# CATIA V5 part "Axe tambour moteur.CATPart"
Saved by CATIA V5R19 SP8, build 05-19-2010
Part number: Axe tambour moteur
Nomenclature: 39a
Material "Acier": density 7860 kg/m3, Young's modulus 2e+11 Pa, Poisson ratio 0.266, thermal expansion 1.17e-05 1/K
Bounding box of the stored display mesh (mm): x -270 to 270, y -7.5 to 7.5, z -7.474 to 7.474
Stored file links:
  C:\Users\rphgr\Desktop\0_Tapis_TC520B_vitesse\Axe tambour moteur.CATPart
  D:\Programmes\DassaultSysteme\win_b64\reffiles\standard\MetricThickPitch.txt
  D:\Programmes\DassaultSysteme\win_b64\startup\materials\French\Catalog.CATMaterial
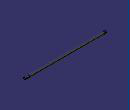
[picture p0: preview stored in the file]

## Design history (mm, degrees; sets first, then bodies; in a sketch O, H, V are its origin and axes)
AxisSystem1: origin (0, 0, 0), X (1, 0, 0), Y (0, 1, 0), Z (0, 0, 1)
Body1 (main body), material "Acier"
  Sketch1 on YZ plane of AxisSystem1, origin (0, 0, 0), H (0, 1, 0), V (0, 0, 1)
    circle A1 centre (0, 0) radius 7.5
    radius A1 = 7.5
  Pad1: profile Sketch1, direction (1, 0, 0), length 270, mirrored extent
  Chamfer1: length 0.5, angle 45, on start face of Pad1; end face of Pad1
  Sketch2 on ZX plane of AxisSystem1, origin (0, 0, 0), H (0, 0, 1), V (1, 0, 0)
    line L1 (6.75, 243) -> (11.7, 243)
    line L2 (11.7, 243) -> (11.7, 241.9)
    line L3 (11.7, 241.9) -> (6.75, 241.9)
    line L4 (6.75, 241.9) -> (6.75, 243)
    line L5 (6.7, -258.9) -> (11.7, -258.9)
    line L6 (11.7, -258.9) -> (11.7, -260)
    line L7 (11.7, -260) -> (6.7, -260)
    line L8 (6.7, -260) -> (6.7, -258.9)
    reference projected line E1 through (0, 0) direction (0, 1) from axis of face of Pad1 from Sketch1.A1
    reference intersected line E2 (7.5, -270) -> (-7.5, -270) from start face of Pad1
    reference projected line E3 through (0, 0) direction (0, 1) from axis of face of Pad1 from Sketch1.A1
    reference intersected line E4 (-7.5, 270) -> (7.5, 270) from end face of Pad1
    distance L5 L7 = 1.1
    distance L8 E1 = 6.7
    distance L6 L8 = 5
    distance L7 E2 = 10
    distance L4 E3 = 6.75
    distance L1 L3 = 1.1
    distance L1 E4 = 27
    horizontal: L1 H, L3 H, L5 H, L7 H
    vertical: L2 V, L4 V, L6 V, L8 V
    coincidence: L6 L2
  Groove1: profile Sketch2, axis axis of face of Pad1 from Sketch1.A1, angle 360
  Plane1: type Offset, RefPlane ZX plane of AxisSystem1, Offset 7.5, reversed
  Sketch3 on Plane1, origin (7.7174, -7.5, -10.4756), H (1, 0, 0), V (0, 0, -1)
    point P1 (252.2826, -10.4756)
    reference intersected point E1 (262.2826, -10.4756) from end face of Pad1
    reference projected line E2 through (0, -10.4756) direction (1, 0) from axis of face of Pad1 from Sketch1.A1
    distance E1 P1 = 10
    coincidence: P1 E2
  Hole1: placed by Sketch3, at (260, -7.5, 0) direction (0, -1, 0), diameter 6.647, through (limit type 3), threaded "M8", thread diameter 8, thread depth 0.042, pitch 1.25
  Chamfer2: length 1.5, angle 45, on edge [face of Pad1 from Sketch1.A1 | face of Hole1]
